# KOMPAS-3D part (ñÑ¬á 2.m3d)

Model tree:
1. Эскиз:1
2. Операция выдавливания:1
     Расстояние 1 = 0.6
3. Эскиз:2
4. Вырезать элемент выдавливания:1
     Толщина стенки 1 = 3; Толщина стенки 2 = 3; Расстояние 1 = 10
5. Эскиз:3
6. Вырезать элемент выдавливания:2
     Толщина стенки 1 = 3; Толщина стенки 2 = 3; Расстояние 1 = 10
7. Эскиз:4
8. Вырезать элемент выдавливания:3
     Толщина стенки 1 = 3; Толщина стенки 2 = 3; Расстояние 1 = 10
9. Эскиз:5
10. Вырезать элемент выдавливания:4
     Толщина стенки 1 = 3; Толщина стенки 2 = 3; Расстояние 1 = 10
